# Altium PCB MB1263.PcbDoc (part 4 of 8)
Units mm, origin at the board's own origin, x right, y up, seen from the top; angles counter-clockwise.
Board outline 86 x 120 mm, 6 copper layers (Top Layer, Signal Layer 1, Signal Layer 2, Signal Layer 3, Signal Layer 4, Bottom Layer), stack 1.556 mm thick; 392 components, 421 nets, 1978 pads, 1444 vias.
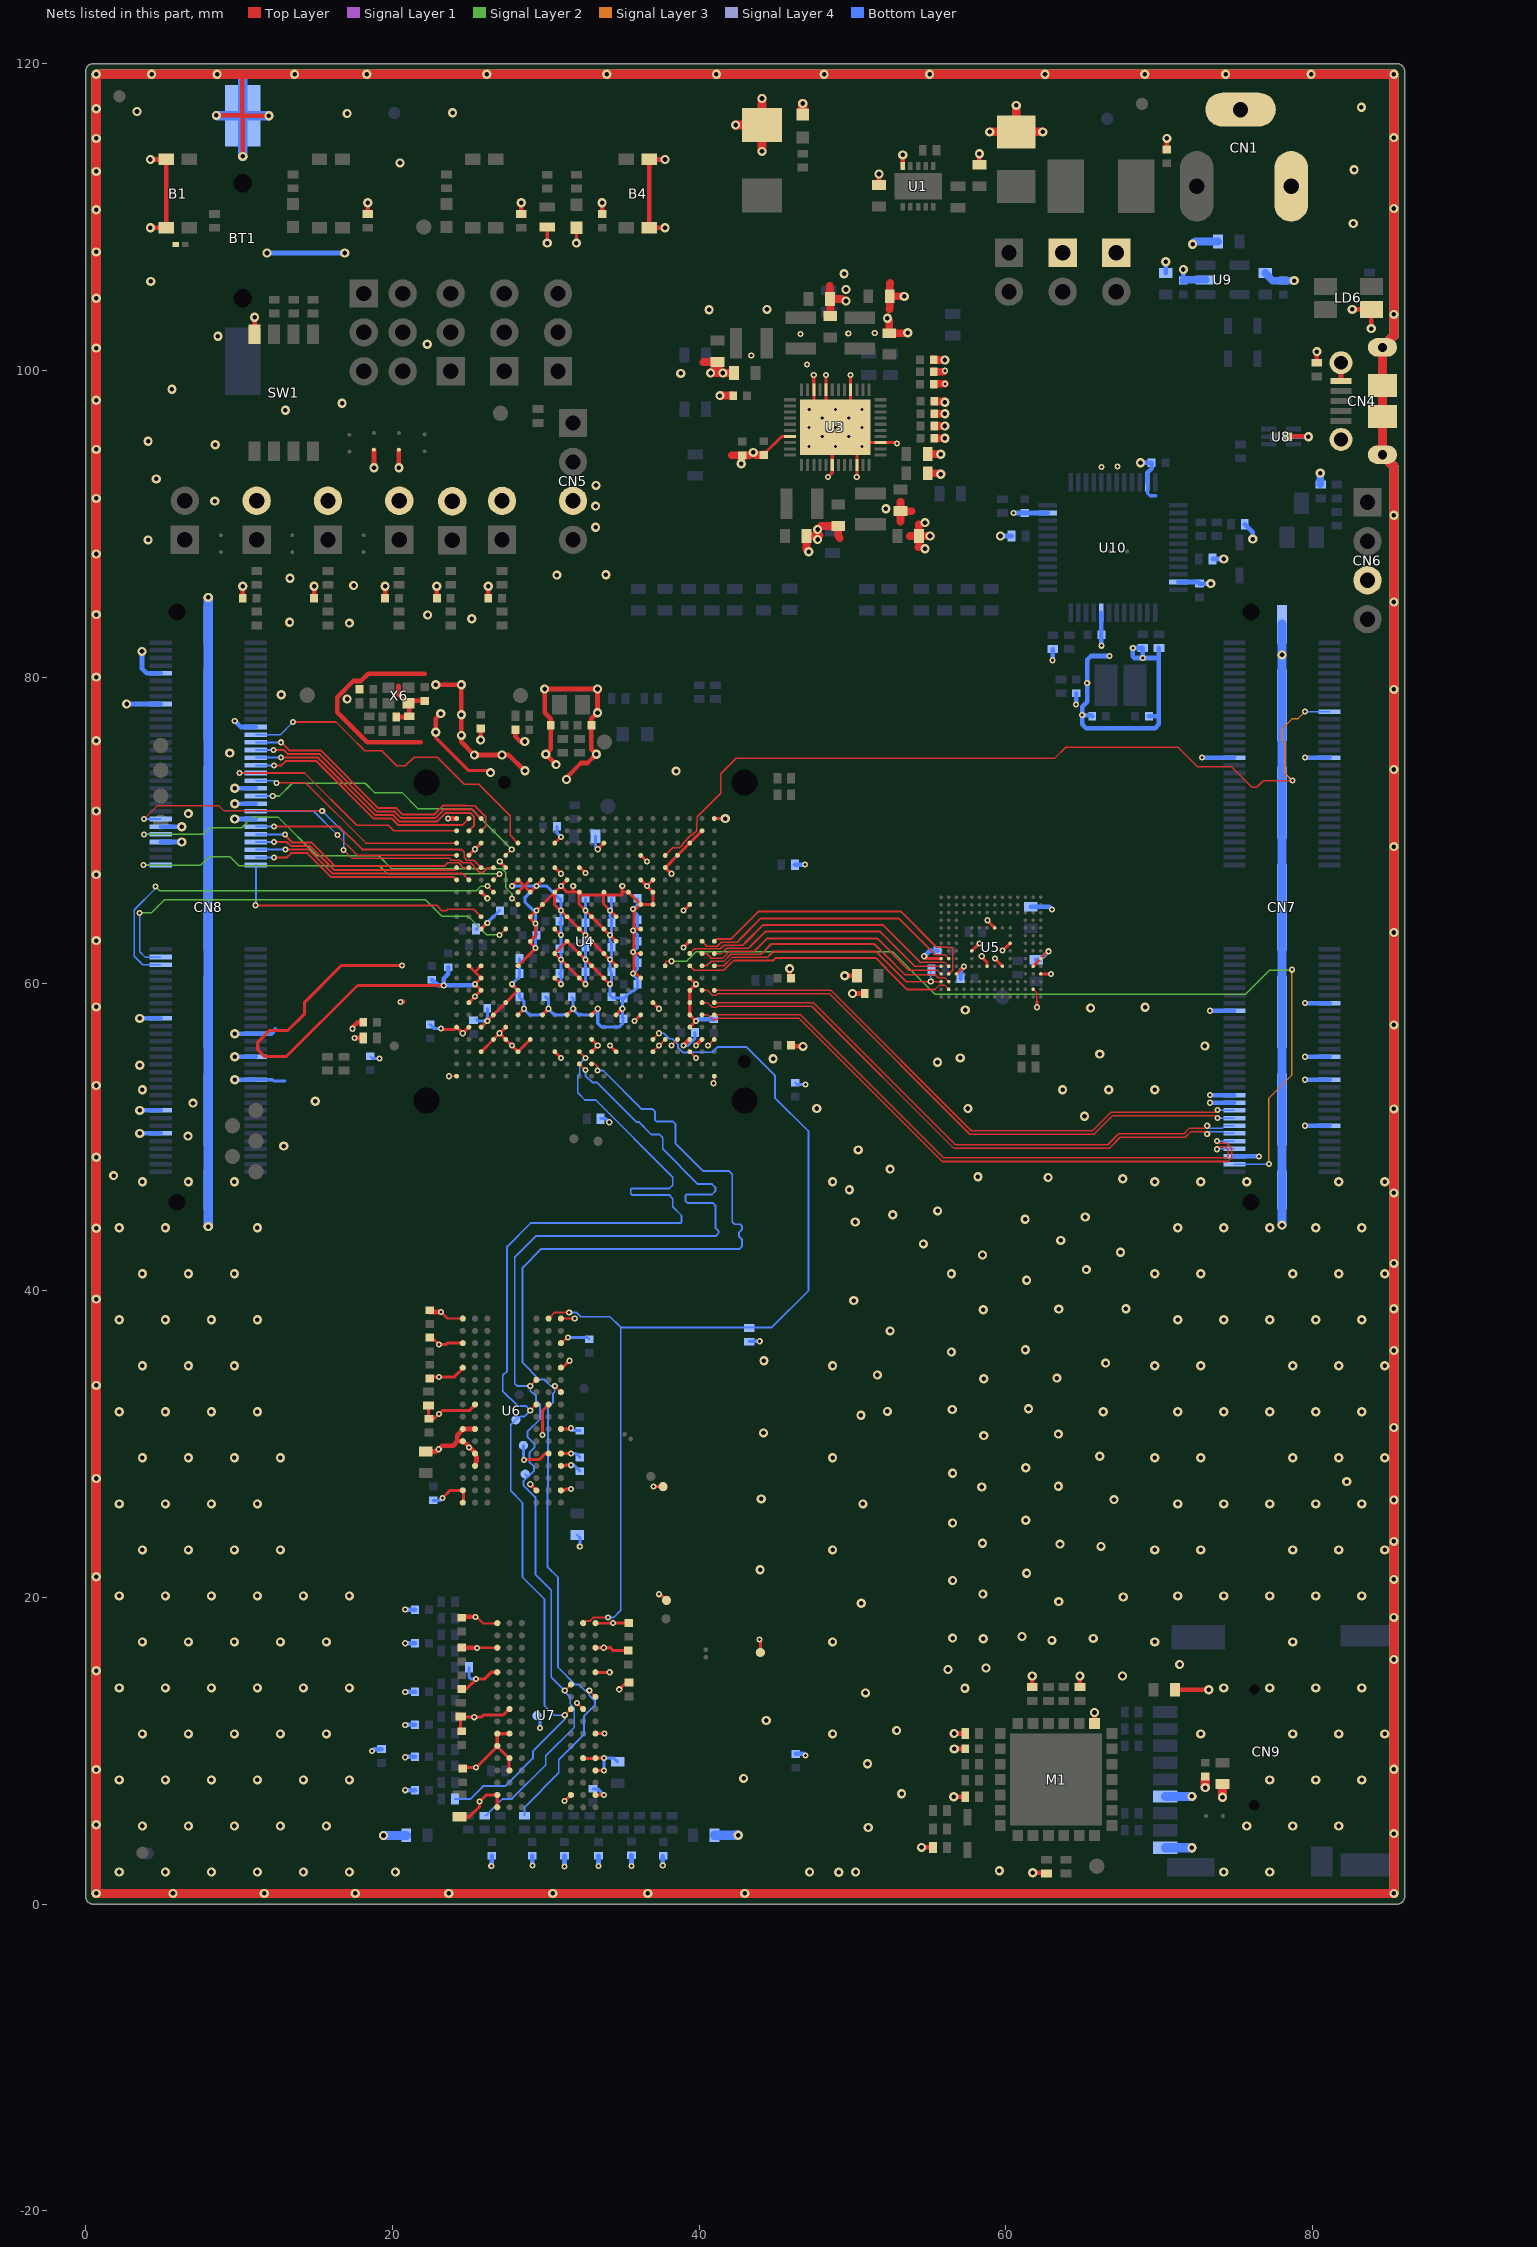
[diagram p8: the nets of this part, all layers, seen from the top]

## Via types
v1: diameter 0.4, hole 0.2, Top Layer to Bottom Layer, tented both sides, 771 vias
v2: diameter 0.6, hole 0.3, Top Layer to Bottom Layer, tented both sides, 670 vias
v3: diameter 0.4, hole 0.2, Top Layer to Bottom Layer, 3 vias

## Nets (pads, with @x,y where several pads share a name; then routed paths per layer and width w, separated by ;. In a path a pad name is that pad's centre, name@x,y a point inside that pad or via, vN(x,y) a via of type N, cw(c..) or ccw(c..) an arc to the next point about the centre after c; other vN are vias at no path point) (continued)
DDR_ODT: R131.1 U4.L21 U6.K1 U7.K1 | length 75.4
  Top Layer w0.12: v1(30.59,33.78) U6.K1@30.99,33.38 ; v1(32.84,13.92) U7.K1@33.24,13.52 ; U4.L21@32.99,54.78 33.21,54.78 33.365,54.625 v1(33.365,54.355)
  Bottom Layer w0.12: R131.1@28.62,5.77 28.62,6.33 30.845,8.555 30.845,9.425 32.5,11.08 32.5,12.28 32.52,12.28 33.2,12.96 33.2,13.269 32.84,13.629 v1(32.84,13.92) 32.83,13.93 32.55,13.93 32.16,14.32 31.931,14.32 30.8,15.451 30.8,21.31 30.104,22.006 30.104,27.185 30.15,27.231 30.15,32.378 30.47,32.698 30.47,33.29 30.59,33.41 v1(30.59,33.78) 30.341,33.78 29.916,34.205 29.585,34.205 28.49,35.3 28.49,41.507 29.703,42.72 42.65,42.72 42.79,42.86 42.79,43.36 42.59,43.56 42.59,43.78 42.79,43.98 42.79,44.23 42.695,44.325 42.335,44.325 42.16,44.5 42.16,47.59 41.96,47.79 40.27,47.79 38.47,49.59 38.47,50.846 38.296,51.02 37.24,51.02 37.12,51.14 37.12,51.684 36.964,51.84 36.256,51.84 33.741,54.355 v1(33.365,54.355)
DDR_RASN: R120.1 TP34.1 U4.M20 U6.J3 U7.J3 | length 77.2
  Top Layer w0.1: U6.J3@29.402,32.599 U6.J3@29.404,32.6
  Top Layer w0.12: v1(28.99,32.18) U6.J3@29.39,32.58 ; v1(31.24,12.32) U7.J3@31.64,12.72 ; U4.M20@32.19,55.58 v1(32.59,55.18)
  Bottom Layer w0.12: R120.1@24.09,6.85 25.07,6.85 25.92,7.7 27.36,7.7 29.165,9.505 29.165,9.985 31.24,12.06 v1(31.24,12.32) 30.54,12.32 29.92,12.94 29.92,19.88 28.484,21.316 28.484,26.176 27.72,26.94 27.72,31.25 TP34.1@28.05,31.58 28.255,31.785 28.595,31.785 v1(28.99,32.18) 28.684,32.486 28.164,32.486 27.2,33.45 27.2,34.473 27.479,34.752 27.479,42.872 29.007,44.4 38.79,44.4 38.85,44.46 38.85,44.9 38.28,45.47 38.28,46 38.04,46.24 35.62,46.24 35.54,46.32 35.54,46.61 35.6,46.67 38.07,46.67 38.28,46.88 38.28,47.404 33.254,52.43 32.56,52.43 32.09,52.9 32.09,54.015 32.215,54.14 32.215,54.805 v1(32.59,55.18)
DDR_RESETN: R103.2 U4.F19 U6.T2 U7.T2 | length 64.4
  Top Layer w0.12: U6.T2@30.19,38.18 30.59,38.58 v1(31.53,38.58) ; U7.T2@32.4,18.31 32.425,18.335 32.549,18.459 32.87,18.459 33.091,18.68 33.37,18.68 33.39,18.7 v1(34.05,18.7) ; U4.F19@36.99,56.38 v1(37.39,56.78)
  Bottom Layer w0.12: v1(31.53,38.58) 31.999,38.58 32.279,38.3 34.19,38.3 34.89,37.6 ; v1(34.05,18.7) 34.41,18.7 34.42,18.69 34.89,19.16 34.89,37.6 ; v1(37.39,56.78) 37.681,56.78 38.041,56.42 38.25,56.42 38.33,56.34 38.339,56.34 38.63,56.049 38.63,55.831 38.931,55.53 39.631,55.53 39.641,55.54 40.87,55.54 41.22,55.89 43.08,55.89 44.94,54.03 44.94,52.588 47.13,50.398 47.13,40 44.73,37.6 43.26,37.6 34.89,37.6
DDR_WEN: R133.1 TP36.1 U4.M21 U6.L3 U7.L3 | length 77.7
  Top Layer w0.12: v1(28.99,33.78) U6.L3@29.39,34.18 ; v1(31.24,13.92) U7.L3@31.64,14.32 ; U4.M21@32.19,54.78 v1(32.59,54.38)
  Bottom Layer w0.12: R133.1@26.02,5.77 26.09,5.77 27.18,6.86 27.79,6.86 30.005,9.075 30.005,9.665 31.86,11.52 31.86,12.791 31.6,13.051 31.6,13.48 31.24,13.84 v1(31.24,13.92) 30.36,14.8 30.36,20.46 29.324,21.496 29.324,26.537 28.54,27.321 28.54,27.57 28.835,27.865 TP36.1@28.85,27.88 ; TP36.1@28.66,28.04 28.82,27.88 TP36.1@28.85,27.88 ; v1(28.99,33.78) 28.99,33.46 29.11,33.34 29.139,33.34 29.37,33.109 29.37,32.82 29.63,32.56 29.63,31.632 28.8,30.802 28.8,30.48 29.26,30.02 29.26,29.76 28.95,29.45 28.95,28.8 29.24,28.51 29.24,28.27 TP36.1@28.85,27.88 ; v1@29.023,33.79 28.99,33.79 28.13,33.79 27.979,33.941 27.979,42.184 29.355,43.56 41.08,43.56 41.28,43.76 41.28,43.876 41.06,44.096 41.06,45.55 40.89,45.72 39.23,45.72 39.12,45.83 39.12,46.21 39.18,46.27 40.84,46.27 41.06,46.49 41.06,46.73 40.84,46.95 39.922,46.95 37.63,49.242 37.63,49.98 37.43,50.18 36.892,50.18 36.072,51 35.908,51 33.328,53.58 33.03,53.58 32.59,54.02 v1(32.59,54.38)
DFSDM_CKOUT: CN8.63 U4.V10 | length 29.4
  Top Layer w0.1: v1@27,63.19 U4.V10@27.39,63.58
  Signal Layer 2 w0.1: v1(3.525,64.625) 4.275,64.625 5.125,65.475 22.175,65.475 23.225,64.425 24.925,64.425 26.16,63.19 v1(26.995,63.19)
  Bottom Layer w0.1: v1(3.525,64.625) 3.525,62.1 3.875,61.75 CN8.63@4.9,61.75
DFSDM_DATA1: CN8.26 U4.U3 | length 21.9
  Top Layer w0.09: 17.7,75.698 18.193,75.205 19.295,75.205 20.275,74.225 20.853,74.225 21.42,74.792 22.922,74.792 24.689,73.025 25.631,73.025 27.695,70.962 27.695,69.675 U4.U3@28.19,69.18
  Top Layer w0.1: v1(13.525,77.075) 16.323,77.075 17.7,75.698
  Bottom Layer w0.1: CN8.26@11.1,76.25 12.7,76.25 v1(13.525,77.075)
DFSDM_DATA3: CN8.65 U4.W7 | length 29.5
  Top Layer w0.1: v1@26.2,66.37 U4.W7@26.59,65.98
  Signal Layer 2 w0.1: v1(4.55,66.35) 4.825,66.075 25.485,66.075 25.785,66.375 v1(26.2,66.375)
  Bottom Layer w0.1: v1(4.55,66.35) 4.55,66.214 3.2,64.864 3.2,64.82 3.175,64.795 3.175,61.8 3.725,61.25 CN8.65@4.9,61.25
DFSDM_DATA5: CN7.20 U4.E4 | length 53.5
  Top Layer w0.09: U4.E4@37.79,68.38 38.285,68.875 38.716,68.875 38.895,69.053 38.895,69.116 39.453,69.675 39.516,69.675 39.829,69.988 39.829,70.519 39.885,70.575 39.885,70.91 41.415,72.44 41.415,73.707 42.433,74.725 42.95,74.725
  Top Layer w0.1: 42.95,74.725 63.2,74.725 63.9,75.425 71.217,75.425 72.492,74.15 74.717,74.15 76.042,72.825 76.35,72.825 76.775,73.25 v1(78.675,73.25)
  Signal Layer 3 w0.1: v1(78.675,73.25) 78.175,73.75 78.175,75.707 78.025,75.857 78.025,76.643 78.682,77.3 79.05,77.3 v1(79.5,77.75)
  Bottom Layer w0.1: v1(79.5,77.75) CN7.20@81.1,77.75
DSI_CK_N: CN7.107 U4.A16 | length 38.4
  Top Layer w0.1: U4.A16@40.99,58.78 47.445,58.78 56.72,49.505 66.64,49.505 67.365,50.23 71.605,50.23 71.975,50.6 72.975,50.6 v1(73.125,50.75)
  Bottom Layer w0.1: v1(73.125,50.75) 73.275,50.6 74.125,50.6 74.275,50.75 CN7.107@74.9,50.75
DSI_CK_P: CN7.109 U4.B16 | length 39.3
  Top Layer w0.1: U4.B16@40.19,58.78 40.551,58.78 40.861,58.47 41.118,58.47 41.198,58.55 47.35,58.55 56.625,49.275 66.735,49.275 67.46,50 71.7,50 72.07,50.37 72.975,50.37 v1(73.125,50.22)
  Bottom Layer w0.1: v1(73.125,50.22) 73.275,50.37 74.155,50.37 74.275,50.25 CN7.109@74.9,50.25
DSI_D0_N: CN7.103 U4.A15 | length 38.3
  Top Layer w0.1: U4.A15@40.99,59.58 48.591,59.58 57.74,50.43 65.655,50.43 66.855,51.63 73.65,51.63 v1(73.8,51.78)
  Bottom Layer w0.1: v1(73.8,51.78) 73.83,51.75 CN7.103@74.9,51.75
DSI_D0_P: CN7.105 U4.B15 | length 39.2
  Top Layer w0.1: U4.B15@40.19,59.58 40.551,59.58 40.861,59.27 41.118,59.27 41.198,59.35 48.495,59.35 57.645,50.2 65.75,50.2 66.95,51.4 73.65,51.4 v1(73.8,51.25)
  Bottom Layer w0.1: v1(73.8,51.25) CN7.105@74.9,51.25
DSI_D1_N: CN7.113 U4.A17 | length 39.8
  Top Layer w0.1: U4.A17@40.99,57.98 46.62,57.98 55.95,48.65 64.425,48.65 64.875,48.65 74.375,48.65 74.5,48.775 74.5,49.175 74.3,49.375 73.937,49.375 73.932,49.37 73.925,49.37 v1(73.775,49.22)
  Bottom Layer w0.1: v1(73.775,49.22) 73.805,49.25 CN7.113@74.9,49.25
DSI_D1_P: CN7.111 U4.B17 | length 41.5
  Top Layer w0.1: U4.B17@40.19,57.98 40.551,57.98 40.861,57.67 41.118,57.67 41.198,57.75 46.525,57.75 55.855,48.42 74.47,48.42 74.73,48.68 74.73,49.27 74.395,49.605 73.92,49.605 v1(73.775,49.75)
  Bottom Layer w0.1: v1(73.775,49.75) CN7.111@74.9,49.75
DSI_RESET: CN8.59 U4.W6 | length 25.6
  Top Layer w0.1: U4.W6@26.59,66.78 v1@26.98,67.17
  Signal Layer 2 w0.1: v1(3.775,67.75) 7.5,67.75 8.025,68.275 9.425,68.275 10,67.7 19.15,67.7 19.68,67.17 v1(26.985,67.17)
  Bottom Layer w0.1: v1(3.775,67.75) CN8.59@4.9,67.75
DSI_TE: CN7.117 U4.E13 | length 58.7
  Top Layer w0.1: U4.E13@37.79,61.18 37.79,61.388 37.876,61.475 v1(38.2,61.475)
  Signal Layer 2 w0.1: v1(38.2,61.475) 39.175,61.475 39.8,62.1 52.6,62.1 55.375,59.325 75.63,59.325 77.205,60.9 78.625,60.9 v1(78.65,60.925)
  Signal Layer 3 w0.1: v1(77.15,48.25) 77.15,52.555 78.65,54.055 v1(78.65,60.925)
  Bottom Layer w0.1: CN7.117@74.9,48.25 v1(77.15,48.25)
EMMC_SDIO2_D0: R900.1 U4.A13 U5.A3 | length 16.8
  Top Layer w0.1: U4.A13@40.99,61.18 41.605,61.18 42.15,61.725 44.45,61.725 44.588,61.863 ; 53.5,60.15 v1(55.1,60.15) U5.A3@55.775,60.15
  Top Layer w0.13: 44.588,61.863 44.85,62.125 51.525,62.125 53.5,60.15
  Bottom Layer w0.09: v1(55.1,60.15) 55.1,60.85 R900.1@55.15,60.9
EMMC_SDIO2_D1: U4.B12 U5.A4 | length 17.2
  Top Layer w0.09: U4.B12@40.19,61.98 40.495,61.98 40.8,61.675 41.458,61.675 41.463,61.68 41.546,61.68 41.548,61.681
  Top Layer w0.1: 41.544,61.685 41.984,62.125 43.6,62.125 43.825,62.35 ; 53.675,60.9 55.525,60.9 U5.A4@55.775,60.65
  Top Layer w0.13: 43.825,62.35 44.45,62.975 51.6,62.975 53.675,60.9
EMMC_SDIO2_D2: U4.A12 U5.A5 | length 16.4
  Top Layer w0.1: U4.A12@40.99,61.98 41.455,61.98 41.8,62.325 43.225,62.325 43.35,62.45 ; 54.1,61.15 U5.A5@55.775,61.15 U5.A5@55.725,61.1
  Top Layer w0.13: 43.35,62.45 44.3,63.4 51.8,63.4 54.05,61.15 54.1,61.15
EMMC_SDIO2_D3: U4.C13 U5.B2 | length 18.4
  Top Layer w0.09: U4.C13@39.39,61.18 39.695,60.875 41.599,60.875 42.124,61.4 ; 55.668,59.9 55.882,59.9
  Top Layer w0.1: 42.124,61.4 42.249,61.525 44.825,61.525 ; 55.373,59.63 55.643,59.9 55.668,59.9 ; 55.882,59.9 56.025,59.9 U5.B2@56.275,59.65
  Top Layer w0.13: 44.825,61.525 44.975,61.675 51.534,61.675 52.175,61.034 52.175,61.02 53.565,59.63 55.373,59.63
EMMC_SDIO2_D4: U4.B13 U5.B3 | length 17.7
  Top Layer w0.09: U4.B13@40.19,61.18 40.48,61.18 40.785,61.485 41.544,61.485 ; 42.067,61.925 44.025,61.925 44.137,62.037 ; 53.426,60.6 55.401,60.6 55.601,60.4 55.949,60.4
  Top Layer w0.1: 41.544,61.485 41.627,61.485 42.067,61.925 ; 52.101,61.925 53.426,60.6 ; 55.949,60.4 56.025,60.4 56.199,60.226 56.199,60.15 U5.B3@56.275,60.15
  Top Layer w0.13: 44.137,62.037 44.7,62.6 51.426,62.6 52.101,61.925
EMMC_SDIO2_D5: U4.A11 U5.B4 | length 19.1
  Top Layer w0.09: 55.475,62.4 56.4,62.4 56.525,62.275 56.525,60.9 U5.B4@56.275,60.65
  Top Layer w0.13: U4.A11@40.99,62.78 41.15,62.94 42.09,62.94 43.875,64.725 53.15,64.725 55.475,62.4
EMMC_SDIO2_D6: U4.C12 U5.B5 | length 18.8
  Top Layer w0.09: U4.C12@39.39,61.98 39.685,62.275 41.375,62.275 41.625,62.525 42.85,62.525 43.025,62.7 ; 55.601,61.4 55.949,61.4
  Top Layer w0.1: 54.425,61.4 55.601,61.4 ; 55.949,61.4 56.025,61.4 U5.B5@56.275,61.15
  Top Layer w0.13: 43.025,62.7 44.15,63.825 52,63.825 54.425,61.4
EMMC_SDIO2_D7: U4.B11 U5.B6 | length 18.1
  Top Layer w0.09: U4.B11@40.19,62.78 40.505,62.465 41.19,62.465 41.45,62.725 42.475,62.725 42.675,62.925 ; 55.601,61.9 55.949,61.9
  Top Layer w0.1: 55.225,62.075 55.4,61.9 55.601,61.9 ; 55.949,61.9 56.025,61.9 U5.B6@56.275,61.65
  Top Layer w0.13: 42.675,62.925 44.025,64.275 53.025,64.275 55.225,62.075
ETH_CLK125: CN8.51 U4.U8 | length 29
  Top Layer w0.1: v1@27.8,65.57 U4.U8@28.19,65.18
  Signal Layer 2 w0.1: v1(3.8,69.75) 7.725,69.75 8.15,70.175 10.175,70.175 10.85,70.85 12.575,70.85 15.075,68.35 19.109,68.35 19.94,67.52 27.13,67.52 27.4,67.249 27.4,66.26 27.8,65.86 v1(27.8,65.575)
  Bottom Layer w0.1: v1(3.8,69.75) CN8.51@4.9,69.75
ETH_GTX_CLK: CN8.46 U4.AB4 | length 14.3
  Top Layer w0.1: v1(16.425,69.7) 16.425,69.675 17.72,68.38 U4.AB4@24.19,68.38
  Bottom Layer w0.1: CN8.46@11.1,71.25 14.875,71.25 v1(16.425,69.7)
ETH_MDC: CN8.38 U4.AB3 | length 14.8
  Top Layer w0.1: v1(12.45,73.1) 14.359,73.1 18.28,69.18 U4.AB3@24.19,69.18
  Bottom Layer w0.1: CN8.38@11.1,73.25 12.3,73.25 v1(12.45,73.1)
ETH_MDINT: CN8.47 U4.W5 | length 26.9
  Top Layer w0.09: 23.725,68.175 23.825,68.075 24.395,68.075 24.585,67.885 25.116,67.885 25.295,67.706 25.295,67.643 25.663,67.275 25.916,67.275 26.221,67.58 U4.W5@26.59,67.58
  Top Layer w0.1: v1(3.8,70.75) 4.65,71.6 8.7,71.6 9.025,71.275 v1(15.425,71.275) ; v1(16.825,68.725) 17.37,68.18 23.72,68.18 23.725,68.175
  Bottom Layer w0.1: v1(3.8,70.75) CN8.47@4.9,70.75 ; v1(15.425,71.275) 16.817,69.883 16.817,68.733 v1(16.825,68.725)
ETH_MDIO: CN8.36 U4.AB2 | length 16.8
  Top Layer w0.09: 19.275,70.35 19.725,70.35 20.095,69.98 20.52,69.98
  Top Layer w0.1: v1(10.025,73.75) 14.275,73.75 17.675,70.35 19.275,70.35 ; 20.52,69.98 U4.AB2@24.19,69.98
  Bottom Layer w0.1: v1(10.025,73.75) CN8.36@11.1,73.75
ETH_RX_CLK: CN8.42 U4.V4 | length 19.4
  Top Layer w0.1: U4.V4@27.39,68.38 v1@27.779,68.77
  Signal Layer 2 w0.1: v1(12.2,72.25) 12.633,72.25 13.466,73.084 18.226,73.084 18.834,72.475 20.625,72.475 21.675,71.425 25.13,71.425 v1(27.785,68.77)
  Bottom Layer w0.1: CN8.42@11.1,72.25 v1(12.2,72.25)
ETH_RX_DV: CN8.60 U4.Y9 | length 17.7
  Top Layer w0.09: 22.65,65.125 22.883,65.125 23.225,64.783 23.519,64.783 23.611,64.875 25.295,64.875 U4.Y9@25.79,64.38
  Top Layer w0.13: v1(11.075,65.125) 22.65,65.125
  Bottom Layer w0.13: v1(11.075,65.125) 11.1,65.15 CN8.60@11.1,67.75
ETH_RXD0: CN8.58 U4.AB6 | length 13.9
  Top Layer w0.13: v1(12.275,68.25) 13.13,68.25 13.4,68.52 14.454,68.52 16.009,66.965 24.005,66.965 U4.AB6@24.19,66.78
  Bottom Layer w0.13: CN8.58@11.1,68.25 v1(12.275,68.25)
ETH_RXD1: CN8.56 U4.AA6 | length 14.7
  Top Layer w0.13: v1(13.025,68.75) 14.549,68.75 16.104,67.195 24.575,67.195 U4.AA6@24.99,66.78
  Bottom Layer w0.13: CN8.56@11.1,68.75 v1(13.025,68.75)
ETH_RXD2: CN8.54 U4.AB5 | length 13.9
  Top Layer w0.13: v1(12.275,69.25) 13.125,69.25 13.395,68.98 14.645,68.98 16.2,67.425 24.035,67.425 U4.AB5@24.19,67.58
  Bottom Layer w0.13: CN8.54@11.1,69.25 v1(12.275,69.25)
ETH_RXD3: CN8.52 U4.AA5 | length 15
  Top Layer w0.09: 23.6,67.885 24.316,67.885 24.621,67.58 U4.AA5@24.99,67.58
  Top Layer w0.13: v1(13,69.75) 13,69.7 13.49,69.21 14.74,69.21 16.275,67.675 23.39,67.675 23.6,67.885
  Bottom Layer w0.13: CN8.52@11.1,69.75 v1(13,69.75)
ETH_TX_EN: CN8.50 U4.Y5 | length 16
  Top Layer w0.09: 24.685,68.59 24.685,68.253 24.863,68.075 25.295,68.075 U4.Y5@25.79,67.58
  Top Layer w0.13: v1(12.275,70.25) 16.55,70.25 18.025,68.775 24.5,68.775 24.685,68.59
  Bottom Layer w0.13: CN8.50@11.1,70.25 v1(12.275,70.25)
ETH_TXD0: CN8.34 U4.AA1 | length 15.9
  Top Layer w0.13: v1(12.275,74.25) 12.766,74.25 13.036,74.52 15.055,74.52 18.8,70.775 19.975,70.775 20.4,70.35 24.56,70.35 U4.AA1@24.99,70.78
  Bottom Layer w0.13: CN8.34@11.1,74.25 v1(12.275,74.25)
ETH_TXD1: CN8.32 U4.AA2 | length 17.3
  Top Layer w0.13: v1(12.75,74.75) 15.15,74.75 18.895,71.005 20.07,71.005 20.495,70.58 22.904,70.58 23.469,71.145 25.084,71.145 25.315,70.914 25.315,70.305 U4.AA2@24.99,69.98
  Bottom Layer w0.13: CN8.32@11.1,74.75 v1(12.75,74.75)
ETH_TXD2: CN8.30 U4.Y1 | length 17
  Top Layer w0.13: v1(12.25,75.25) 12.925,75.25 13.175,75 15.226,75 18.991,71.235 20.166,71.235 20.591,70.81 22.809,70.81 23.374,71.375 25.195,71.375 U4.Y1@25.79,70.78
  Bottom Layer w0.13: CN8.30@11.1,75.25 v1(12.25,75.25)
ETH_TXD3: CN8.28 U4.Y2 | length 18.5
  Top Layer w0.09: 24.726,71.626 25.375,71.626 26.095,70.906 26.095,70.285 U4.Y2@25.79,69.98
  Top Layer w0.13: v1(12.75,75.75) 13.27,75.23 15.321,75.23 19.086,71.465 20.261,71.465 20.686,71.04 22.713,71.04 23.299,71.626 24.726,71.626
  Bottom Layer w0.13: CN8.28@11.1,75.75 v1(12.75,75.75)
GND: B1.3 B1.4 B4.1 B4.2 BT1.2 C1.2 C2.1 C3.1 C4.1 C5.1 C6.1 C7.1 C8.1 C9.1 C10.1 C11.1 C12.1 C13.1 C14.1 C15.1 C16.1 C17.1 C18.1 C19.1 C20.2 C21.1 C22.1 C23.1 C24.1 C25.1 C26.1 C27.1 C28.1 C29.1 C30.1 C31.1 C32.1 C33.1 C34.1 C35.1 C36.2 C37.1 C38.1 C39.2 C40.1 C41.1 C42.2 C43.1 C44.2 C45.2 C46.2 C47.2 C48.1 C49.2 C50.2 C51.2 C52.2 C53.2 C54.2 C55.1 C56.2 C57.2 C58.1 C59.1 C60.1 C61.2 C62.2 C63.1 C64.1 C65.2 C66.2 C67.1 C68.1 C69.1 C70.1 C71.1 C72.2 C73.2 C74.2 C75.1 C76.1 C77.1 C78.1 C79.1 C80.1 C81.2 C82.1 C83.1 C84.1 C85.1 C86.1 C87.1 C88.1 C89.1 C90.1 C91.1 C92.1 C93.1 C94.1 C95.2 C96.1 C97.1 C98.1 C99.1 C100.1 C101.1 C102.1 C103.1 C104.1 C105.1 C106.1 C107.1 C108.1 C109.1 C110.1 C111.1 C112.1 C113.1 C114.1 C115.2 C116.2 C117.2 C118.2 C119.2 C120.2 C121.2 C122.1 C123.2 C124.2 C125.2 C126.2 C127.2 C128.2 C129.2 C130.1 C131.2 C132.2 C133.1 C134.1 C135.2 C136.2 C137.2 C138.2 C139.2 C140.2 C300.1 CN1.2 CN1.3 CN4.5 CN4.6 CN4.7 CN4.8 CN4.9 CN4.10 CN4.11 CN5.3 CN6.3 CN7.31 CN7.32 CN7.76 CN7.77 CN7.90 CN7.96 CN7.99 CN7.101 CN7.108 CN7.115 CN7.121 CN7.122 CN7.123 CN7.124 CN7.125 CN7.126 CN7.127 CN7.128 CN8.9 CN8.17 CN8.24 CN8.40 CN8.44 CN8.48 CN8.49 CN8.53 CN8.79 CN8.84 CN8.90 CN8.96 CN8.103 CN8.109 CN8.121 CN8.122 CN8.123 CN8.124 CN8.125 CN8.126 CN8.127 CN8.128 CN9.6 CN9.9 D1.1 JP1.1 JP2.1 JP7.2 JP8.2 JP9.2 JP10.2 JP11.2 LD1.2 LD4.2 LD5.2 LD6.1 M1.21 R9.2 R10.2 R14.1 R32.1 R36.1 R37.1 R40.1 R41.1 R44.1 R47.1 R48.1 R55.1 R65.2 R69.2 R73.1 R74.2 R88.2 R89.2 R91.1 R97.2 R98.2 R102.2 R103.1 R108.1 R303.2 SB2.1 SB3.1 SW1.4 TP23.1 TP24.1 TP26.1 TP35.1 TP37.1 U1.10 U2.2 U3.6 U3.10 U3.15 U3.26 U3.30 U3.32 U3.41 U3.ep U4.A1 U4.A19 U4.A22 U4.AA4 U4.AA13 U4.AA16 U4.AA18 U4.AB1 U4.AB18 U4.AB22 U4.B2 U4.B19 U4.C3 U4.C8 U4.C11 U4.C14 U4.C15 U4.C16 U4.C17 U4.C18 U4.C19 U4.C20 U4.D4 U4.D19 U4.E5 U4.E19 U4.F6 U4.F7 U4.F8 U4.F16 U4.F20 U4.G4 U4.G6 U4.G8 U4.G10 U4.G12 U4.G14 U4.G17 U4.H7 U4.J9 U4.J11 U4.J13 U4.J17 U4.J20 U4.K3 U4.K7 U4.K10 U4.K12 U4.K14 U4.L9 U4.L11 U4.L13 U4.L17 U4.L19 U4.L20 U4.M5 U4.M7 U4.M10 U4.M12 U4.M14 U4.N6 U4.N9 U4.N11 U4.N13 U4.N17 U4.P3 U4.P5 U4.P7 U4.P10 U4.P12 U4.P14 U4.P20 U4.R6 U4.R8 U4.R17 U4.T6 U4.T7 U4.T9 U4.T11 U4.T19 U4.U6 U4.U7 U4.U13 U4.U15 U4.U17 U4.U20 U4.V5 U4.V16 U4.V18 U4.V19 U4.W17 U4.W19 U4.Y3 U4.Y7 U4.Y10 U4.Y13 U4.Y14 U4.Y15 U4.Y18 U4.Y20 U5.A6 U5.C4 U5.E7 U5.G5 U5.H10 U5.J5 U5.K8 U5.N2 U5.N5 U5.P4 U5.P6 U6.A9 U6.B1 U6.B3 U6.B9 U6.D1 U6.D8 U6.E1 U6.E2 U6.E8 U6.F9 U6.G1 U6.G8 U6.G9 U6.J2 U6.J8 U6.M1 U6.M9 U6.P1 U6.P9 U6.T1 U6.T9 U7.A9 U7.B1 U7.B3 U7.B9 U7.D1 U7.D8 U7.E1 U7.E2 U7.E8 U7.F9 U7.G1 U7.G8 U7.G9 U7.J2 U7.J8 U7.M1 U7.M9 U7.P1 U7.P9 U7.T1 U7.T9 U8.2 U9.2 U10.8 U10.23 U10.35 U10.47 X6.2 | length 2663.5
  Top Layer w0.09: 62.025,58.85 62.025,59.257
  Top Layer w0.1: U5.N2@61.775,59.65 62.025,59.4 62.025,59.257
  Top Layer w0.12: v1(23.69,53.98) U4.AB22@24.19,53.98 ; v1@29.048,27.322 v1@29.048,27.38 ; U6.M1@30.99,34.98 U6.M1@31.09,34.98 ; v1@31.59,30.98 v1(31.64,31.03) ; U4.M5@32.19,67.58 U4.M5@32.19,67.63 ; U4.F20@36.99,55.58 v1(37.39,55.98) U4.E19@37.79,56.38 ; v1(37.39,20.21) v1@37.47,20.21 ; v1(38.19,55.98) U4.D19@38.59,56.38 ; U4.C20@39.39,55.58 v1(39.79,55.18) ; v1(40.59,55.98) U4.A19@40.99,56.38 ; v1(40.94,53.52) 40.99,53.57 U4.A22@40.99,53.98
  Top Layer w0.15: v1@23.17,38.61 23.175,38.605 23.6,38.18 U6.T9@24.59,38.18 U6.T9@24.64,38.18 ; U6.M9@24.59,34.93 U6.M9@24.59,34.98 ; v1(25.41,18.73) 25.495,18.73 25.92,18.305 26.825,18.305 U7.T9@26.84,18.32 ; v1(25.52,16.71) U7.P9@26.8,16.71 ; U6.T1@30.99,38.18 v1(31.89,38.18) ; U6.P1@31.015,36.555 31.4,36.94 v1(31.45,36.94) ; U7.T1@33.2,18.31 33.24,18.31 v1@34.39,18.31
  Top Layer w0.2: v1(20.625,61.2) 16.675,61.2 14.279,58.804 14.279,58.054 13.2,56.975 12,56.975 11.225,56.2 11.225,55.7 11.65,55.275 13.1,55.275 17.725,59.9 v1(23.35,59.9) ; R36.1@22.315,32.38 22.36,32.335 C47.2@22.36,31.65 ; C47.2@22.39,31.65 22.72,31.65 v1(23.03,31.96) 23.25,32.18 25.013,32.18 25.401,32.569 U6.J8@25.433,32.6 ; C46.2@22.44,34.18 22.44,34.205 22.467,34.232 22.615,34.38 v1(23.04,34.38) 24.04,34.38 U6.M9@24.59,34.93 ; C45.2@22.53,36.84 C45.2@22.43,36.94 22.59,36.94 v1(23.04,36.49) 23.51,36.49 23.62,36.6 24.57,36.6 U6.P9@24.59,36.58 ; v2(22.825,76.4) 22.825,76.056 24.956,73.925 26.255,73.925 v2(26.401,73.779) ; v1(23.165,57.08) 23.215,57.03 24.04,57.03 U4.AB18@24.19,57.18 v1(24.59,56.78) U4.AA18@24.99,57.18 ; v1(23.27,26.48) 23.77,26.98 U6.B9@24.59,26.98 ; C59.1@24.38,5.7 25.02,5.7 25.69,6.37 v1(25.69,6.69) 26.12,7.12 U7.B9@26.84,7.12 26.84,6.35 26.825,6.335 U7.A9@26.79,6.3 ; C53.2@24.52,14.02 24.82,14.02 24.82,14.03 v1(25.46,14.67) 25.995,14.67 26.445,15.12 U7.M9@26.84,15.12 ; C65.2@24.53,11.27 24.525,11.275 24.45,11.35 R55.1@24.45,12.23 24.49,12.19 v1(25.34,12.19) 25.79,12.19 25.93,12.33 27.22,12.33 U7.J8@27.6,12.71 ; C66.2@24.58,8.85 24.64,8.91 v1(25.46,8.91) U7.F9@26.83,10.28 ; U6.A9@24.64,26.18 U6.B9@24.64,26.98 ; U4.AA16@24.99,58.78 v1(25.39,59.18) U4.Y15@25.79,59.58 ; U4.AA13@24.99,61.22 U4.AA13@24.99,61.18 25.39,60.78 ; U4.AA4@24.99,68.38 v1(25.39,68.78) U4.Y3@25.79,69.18 ; U4.Y7@25.79,65.98 v1(26.19,65.58) ; U4.Y20@25.79,55.58 U4.W19@26.59,56.38 ; U4.Y18@25.79,57.18 v1(26.19,57.58) U4.W17@26.59,57.98 U4.V16@27.39,58.78 U4.U15@28.19,59.58 ; U4.Y15@25.79,59.58 v1(25.39,59.98) U4.Y14@25.79,60.38 25.39,60.78 ; U4.Y13@25.79,61.18 25.39,60.78 ; U4.Y10@25.79,63.58 v1(26.19,63.98) ; U4.W19@26.59,56.38 v1(26.99,56.78) ; U7.F9@26.8,10.31 26.815,10.295 U7.F9@26.83,10.28 ; U7.G9@26.84,11.12 U7.G9@26.84,11.11 ; v1@27,67.97 U4.V5@27.39,67.58 ; U4.V18@27.39,57.18 v1(26.99,56.78) ; U7.D8@27.6,8.71 27.6,8.72 27.6,9.51 U7.F9@26.83,10.28 ; U7.G8@27.6,11.11 U7.G9@26.84,11.11 ; v1(27.79,59.98) U4.U15@28.19,59.58 ; v1(27.79,66.38) 27.86,66.45 27.925,66.515 U4.U6@28.19,66.78 28.59,66.38 ; U4.U17@28.19,57.98 v1(28.59,58.38) ; U4.U13@28.19,61.18 v1(29.34,62.33) 28.99,62.68 U4.T11@28.99,62.78 29.34,63.13 v1(29.34,63.93) 28.99,64.28 U4.T9@28.99,64.38 v1(29.39,64.78) U4.R8@29.79,65.18 U4.P7@30.565,65.955 ; U4.U7@28.19,65.98 28.198,65.988 28.59,66.38 ; v1@28.59,28.98 29.57,28.98 29.97,29.38 U6.E2@30.19,29.38 U6.E2@30.24,29.38 ; U4.T19@28.99,56.38 28.66,56.05 U4.U20@28.19,55.58 v1(27.79,55.98) U4.V19@27.39,56.38 v1(26.99,56.78) ; U4.T6@28.99,66.78 28.59,66.38 ; v1@29.048,27.322 U6.B3@29.39,26.98 ; v1(29.79,30.58) 29.79,32.18 U6.J2@30.19,32.58 ; U4.R17@29.79,57.98 v1(30.19,58.38) ; U4.R6@29.79,66.78 v1(29.39,66.38) U4.T7@28.99,65.98 28.59,66.38 ; v2(30.1,108.3) LD5.2@30.1,109.35 ; U4.P20@30.59,55.58 v1(30.99,55.18) ; U4.P14@30.59,60.38 v1(30.99,59.98) ; U4.P10@30.59,63.58 v1(30.99,63.18) ; U4.P5@30.59,67.58 v1(30.99,67.18) ; U4.P3@30.59,69.18 v1(30.99,69.58) ; U6.B1@30.99,26.98 31.22,26.98 31.32,27.08 v1(31.64,27.08) ; U6.D1@30.99,28.58 31.25,28.58 31.3,28.63 31.63,28.63 v1(31.64,28.62) ; U6.E1@30.99,29.38 v1(31.64,29.38) v1@31.725,29.38 ; U6.G1@30.99,30.98 v1@31.59,30.98 ; U6.M1@31.09,34.98 v1(31.54,35.43) ; v1(31.23,6.725) U7.B3@31.625,7.12 ; U4.N17@31.39,57.98 v1(31.79,58.38) ; U4.N6@31.39,66.78 v1(30.99,66.38) ; v1(31.79,66.38) 31.79,65.98 ; v2(32,108.3) LD4.2@32,109.3 ; v1(32.04,13.12) U7.J2@32.44,12.72 ; U4.M5@32.19,67.63 32.215,67.605 v1(32.59,67.23) ; U7.E2@32.44,9.51 U7.E1@33.24,9.51 ; v1(32.59,59.98) 32.19,60.38 31.39,61.18 v1(30.99,61.58) U4.P12@30.59,61.98 U4.N11@31.39,62.78 32.19,61.98 32.19,61.97 32.2,61.97 v1(32.59,61.58) 32.99,61.18 U4.K14@33.79,60.38 v1(34.19,59.98) ; U4.L20@32.99,55.58 v1(33.39,55.98) U4.L19@32.99,56.38 ; U4.L17@32.99,57.98 v1(33.39,58.38) ; U7.M1@33.2,15.11 33.24,15.11 v1@34.17,15.11 ; U7.B1@33.24,7.12 v1(33.79,7.12) ; U7.D1@33.24,8.72 v1(33.79,8.72) ; U7.E1@33.24,9.52 v1(33.79,9.52) ; U7.G1@33.24,11.12 v1(33.83,11.12) ; U7.P1@33.24,16.72 v1(33.78,16.72) 34.22,16.72 34.41,16.53 C52.2@35.39,16.53 ; v1(33.39,68.78) U4.K3@33.79,69.18 ; v1(34.19,55.98) U4.J20@34.59,55.58 ; v1(34.39,18.33) C50.2@35.4,18.33 ; U4.J17@34.59,57.98 v1(34.99,58.38) ; U4.J13@34.59,61.18 v1(34.19,61.58) U4.K12@33.79,61.98 32.99,62.78 v1(32.59,63.18) 32.19,63.58 31.39,64.38 v1(30.99,64.78) 30.94,64.78 30.565,65.155 U4.P7@30.565,65.955 ; U4.J11@34.59,62.78 v1(34.19,63.18) U4.K10@33.79,63.58 32.99,64.38 v1(32.59,64.78) 32.165,65.205 32.165,65.955 U4.M7@32.19,65.98 ; U4.J9@34.59,64.38 v1(34.19,64.78) 33.765,65.205 U4.K7@33.765,65.955 ; v1(34.79,14.01) 35.23,14.45 C54.2@35.43,14.45 ; v1(34.99,66.38) 34.965,66.355 34.965,65.98 ; v1(35.79,57.58) U4.G17@36.19,57.98 ; U4.G14@36.19,60.38 35.89,60.68 v1(35.69,60.68) 35.75,60.74 v1@35.75,62.02 ; U4.G12@36.19,61.98 35.79,61.98 v1@35.75,62.02 ; U4.G10@36.19,63.58 35.79,63.58 v1@35.75,63.54 ; U4.G6@36.19,66.78 v1(36.59,66.38) ; U4.G4@36.19,68.38 v1(36.59,67.98) ; U4.F6@36.99,66.78 v1(36.59,66.38) ; U4.F16@36.99,58.78 v1(37.39,58.38) ; v1(37.02,27.22) TP23.1@37.65,27.22 ; v1@37.47,20.21 TP24.1@37.87,19.81 ; v1(38.19,67.18) U4.E5@37.79,67.58 U4.D4@38.59,68.38 U4.C3@39.39,69.18 U4.B2@40.19,69.98 ; v1(38.99,62.38) U4.C11@39.39,62.78 ; v1(38.99,64.78) U4.C8@39.39,65.18 ; U4.C18@39.39,57.18 v1(39.79,57.58) U4.C17@39.39,57.98 U4.C16@39.39,58.78 U4.C15@39.39,59.58 39.39,59.585 39.755,59.95 39.755,59.98 39.755,60.03 39.397,60.387 U4.C14@39.395,60.39 ; U4.A1@40.99,70.78 41.705,70.78 v2(41.71,70.775) ; v1(43.94,17.25) 43.99,17.2 TP26.1@43.99,16.41 ; C20.2@44.202,94.51 45.378,95.686 U3.41@45.929,95.686 ; U3.ep@46.814,95.686 U3.ep@46.9,95.6 ; v1(47.475,99.7) 47.475,98.74 U3.32@47.479,98.736 47.479,98.021 U3.ep@47.5,98 ; v1@48.279,99.7 U3.30@48.279,98.736 48.279,97.921 U3.ep@48.3,97.9 ; v1(48.396,93.05) 48.679,93.333 U3.6@48.679,93.836 48.679,94.579 U3.ep@48.7,94.6 ; v1(49.875,99.7) 49.879,99.696 U3.26@49.879,98.736 49.879,97.721 U3.ep@49.9,97.7 ; v1(50.275,93.05) 50.279,93.054 U3.10@50.279,93.836 50.279,94.679 U3.ep@50.3,94.7 ; U3.ep@51,95.3 51.014,95.286 U3.15@51.829,95.286 52.839,95.286 v1(52.9,95.225) ; v1(54.675,61.8) 54.825,61.65 U5.A6@55.775,61.65 ; U5.C4@56.775,60.65 57.25,61.125 v1(57.275,61.125) ; U5.E7@57.775,62.15 58.25,62.625 v1(58.275,62.625) ; v1(58.425,61.8) 58.425,61.75 58.775,61.4 U5.G5@58.775,61.15 ; v1(58.8,64.15) 58.8,64.125 U5.H10@59.275,63.65 ; v1(59.3,61.65) 59.3,61.625 U5.J5@59.775,61.15 ; v1(59.775,62.175) 59.8,62.175 U5.K8@60.275,62.65 ; U5.N5@61.775,61.15 U5.P6@62.275,61.65 62.75,62.125 v1(62.775,62.125) ; v1(62.025,58.475) 62.025,58.85 ; U5.P4@62.275,60.65 v1(62.95,60.65) ; U7.F9@26.83,10.28 26.84,10.29 U7.F9@26.84,10.32 U7.G9@26.84,11.11 ; U4.P7@30.565,65.955 U4.P7@30.59,65.98 v1(30.99,66.38) ; v1(30.99,66.38) 31.39,65.98 31.79,65.98 ; 31.79,65.98 U4.M7@32.19,65.98 ; U4.M7@32.19,65.98 32.37,65.8 33.61,65.8 U4.K7@33.765,65.955 ; U4.K7@33.765,65.955 U4.K7@33.79,65.98 33.969,65.8 34.965,65.8 34.965,65.98 ; 34.965,65.98 U4.H7@35.39,65.98 U4.G8@36.19,65.18 ; v1@35.75,62.02 v1(35.69,62.08) 35.75,62.14 35.75,63.42 v1(35.69,63.48) v1@35.75,63.54 ; v1@35.75,63.54 35.75,64.82 v1(35.69,64.88) 35.89,64.88 U4.G8@36.19,65.18 ; U4.G8@36.19,65.18 U4.F8@36.99,65.18 U4.F7@36.99,65.98 v1(36.59,66.38)
  Top Layer w0.3: v2(4.225,109.3) B1.4@5.25,109.3 B1.3@5.25,113.75 v2(4.225,113.75) ; v2(8.525,116.625) 10.225,116.625 ; 10.225,119.3 10.225,116.625 ; C28.1@10.25,85.15 v2(10.25,85.925) ; v2(10.25,113.95) 10.25,116.55 10.225,116.575 10.25,116.6 ; SW1.4@11.015,102.345 v2(11.015,103.46) ; v2(11.95,116.6) 10.25,116.6 ; C29.1@14.9,85.15 v2(14.9,85.925) ; v1(17.4,57.075) 17.4,57.168 17.732,57.5 C42.2@18.1,57.5 ; v1(17.525,56.475) R32.1@18.1,56.475 ; R9.2@18.4,110.2 v2(18.4,110.925) ; v2(18.8,93.65) SB2.1@18.8,94.825 ; C30.1@19.525,85.15 v2(19.525,85.925) ; C35.1@20.25,77.4 21.05,77.4 R303.2@21.1,77.45 21.1,78.25 X6.2@21.05,78.3 ; 20.4,79.425 20.4,78.861 20.961,78.3 X6.2@21.05,78.3 ; v2(20.425,93.65) SB3.1@20.425,94.825 ; v1(20.525,58.825) v1@20.7,58.825 ; 21.85,75.75 18.356,75.75 16.4,77.706 16.4,78.694 17.451,79.745 17.945,79.745 18.425,80.225 22.1,80.225 ; C33.1@22.1,78.45 21.2,78.45 X6.2@21.05,78.3 ; C48.1@22.18,29.51 22.87,29.51 v1(23.02,29.66) 23.26,29.9 23.96,29.9 24.24,30.18 ; C44.2@22.43,38.61 v1@23.17,38.61 ; v2(22.825,76.4) 22.825,77.3 v2(23.15,77.625) ; v2(22.825,79.5) v2(24.5,79.5) v2(24.5,77.55) v2(24.5,76.2) 24.5,75.775 v2(25.35,74.925) v2(27.15,74.925) 27.6,74.925 28.625,73.9 v2(28.65,73.9) ; C31.1@22.9,85.145 v2(22.9,85.92) ; v1(23.62,70.78) U4.AB1@24.19,70.78 ; C51.2@24.52,16.73 24.54,16.71 v1(25.52,16.71) ; C49.2@24.53,18.67 24.59,18.73 v1(25.41,18.73) ; U6.G9@24.59,30.98 U6.G9@24.64,30.98 ; U6.F9@24.633,30.2 25.021,29.811 25.421,29.411 25.433,29.4 25.433,29.38 25.433,29.267 25.483,29.216 25.483,28.844 25.433,28.793 U6.D8@25.433,28.652 ; U6.F9@24.64,30.18 U6.F9@24.59,30.18 24.24,30.18 ; U6.G8@25.39,30.98 U6.G9@24.64,30.98 ; v2(25.75,75.9) C34.1@25.75,76.65 ; C32.1@26.25,85.145 v2(26.25,85.92) ; C38.1@28.025,76.575 28.025,76.1 28.325,75.8 v2(28.625,75.8) ; R10.2@28.4,110.2 v2(28.4,110.925) ; 29.925,77.675 30.325,77.275 C36.2@30.325,76.85 30.325,75.3 v2(30,74.975) v2(30.675,74.3) ; 29.925,77.696 v2(29.925,79.225) v2(33.375,79.225) v2@33.375,77.696 ; v2(31.35,73.325) 31.35,73.45 32.3,74.4 32.725,74.4 v2(33.3,74.975) 32.975,75.3 C37.1@32.975,76.85 32.975,77.296 33.364,77.686 v2@33.375,77.696 ; v2(33.375,77.675) v2@33.375,77.696 ; C5.1@33.675,110.2 v2(33.675,110.925) ; v2(37.775,109.3) B4.2@36.75,109.3 B4.1@36.75,113.75 v2(37.775,113.75) ; v1(38.99,55.98) U4.C19@39.39,56.38 ; v1(39.79,55.98) U4.B19@40.19,56.38 ; v2(45.9,61) 45.9,60.475 C40.1@46,60.375 ; C43.1@46,56 46.025,56.025 46.125,55.925 v2(46.775,55.925) ; C9.1@48.475,103.6 48.488,103.613 48.525,103.65 C6.1@48.525,104.65 ; v2(49.5,60.525) C39.2@50.3,60.525 ; v2(50,59.375) C41.1@50.8,59.375 ; C4.1@51.725,112.075 v2(51.725,112.8) ; U1.10@53.275,113.325 v2(53.275,114.05) ; v2@54.4,3.7 v2(54.5,3.7) R47.1@55.25,3.7 ; C13.1@55.3,99.15 C13.1@55.325,99.125 ; v2(56.6,7) R44.1@57.35,7 ; v2(56.625,11.125) R41.1@57.35,11.125 ; v2(56.633,10.124) 57.35,10.124 C56.2@57.358,10.124 ; C3.1@58.275,113.4 v2(58.275,114.125) ; R37.1@61.725,14.15 v2(61.725,14.875) ; v2(61.75,2.05) 62.6,2.05 R48.1@62.65,2 ; R40.1@64.825,14.15 v2(64.825,14.875) ; M1.21@65.775,11.775 v2(65.775,12.5) ; C2.1@70.5,114.4 v2(70.5,115.125) ; C55.1@71.025,13.975 v2(73.225,13.975) ; C18.1@78.395,95.7 v2@79.72,95.7 ; R14.1@80.275,100.5 v2(80.275,101.225) ; CN4.5@81.85,99.3 CN4.7@81.85,100.5 ; v2(82.575,103.975) LD6.1@83.825,103.975 v2(83.825,102.725) ; 10.225,116.625 10.25,116.6 ; 24.24,30.18 24.24,30.58 24.615,30.955 U6.G9@24.64,30.98
  Top Layer w0.35: v1@55.95,99.9 v1(56.025,99.975)
  Top Layer w0.4: C15.1@55.325,97.95 55.337,97.962 C15.1@55.35,97.975 ; v2@55.996,97.975 v2@56.027,98.006
  Top Layer w0.5: 40.275,100.525 40.3,100.55 C8.1@41.2,100.55 C8.1@41.2,100.3 ; v2(40.75,99.825) v2(41.55,99.825) ; v2@40.75,99.85 C8.1@41.2,100.3 ; v2(41.352,98.356) C14.1@42.227,98.356 ; 42.125,94.456 42.752,94.456 C21.1@42.802,94.456 ; C12.1@42.277,99.831 42.271,99.825 v2(41.55,99.825) ; v2(42.752,93.906) 42.752,94.406 C21.1@42.802,94.456 ; C20.2@44.202,94.51 C20.2@44.202,94.481 43.694,94.481 v2(43.525,94.65) 43.331,94.456 C21.1@42.802,94.456 ; v2(47.15,88.175) 47,88.325 C27.1@47,89.2 47.725,89.2 47.829,89.2 47.869,89.24 ; v2(47.725,89.625) 47.95,89.85 C25.1@49.075,89.85 49.075,89.175 49.175,89.075 ; 48.525,105.5 C6.1@48.525,104.65 ; C9.1@48.55,103.55 48.55,104.625 C6.1@48.525,104.65 ; 49.3,104.65 C6.1@48.525,104.65 ; v2(52.275,103.4) 52.4,103.275 C10.1@52.4,102.425 53.575,102.425 v2(53.6,102.45) ; 52.4,103.975 52.425,104 C7.1@52.425,104.825 ; 52.45,105.7 52.425,105.675 C7.1@52.425,104.825 ; 53.125,90.15 C24.1@53.125,90.825 ; 53.125,91.425 C24.1@53.125,90.825 ; v2(53.375,104.825) C7.1@52.425,104.825 ; 53.75,89.175 53.775,89.2 C26.1@54.325,89.2 ; 53.85,90.825 C24.1@53.125,90.825 ; 54.3,88.475 54.325,88.5 C26.1@54.325,89.2 ; 54.325,89.975 C26.1@54.325,89.2 ; C23.1@54.9,93.3 55.75,93.3 55.775,93.3 v2@55.8,93.275 ; C22.1@54.9,94.55 v2@55.7,94.55 ; v2@55.125,89.175 55.1,89.2 v2(55.05,89.2) C26.1@54.325,89.2 ; C67.1@55.3,99.9 v1@55.95,99.9 ; C17.1@55.325,96.375 v2(56.025,96.375) ; C16.1@55.325,97.175 v2(56.025,97.175) ; C13.1@55.325,99.125 v1(56.025,99.125) ; C15.1@55.35,97.975 v2@55.996,97.975 ; C19.1@55.352,95.581 56.025,95.581 v2@56.05,95.581 ; C11.1@55.421,100.675 v2(56.025,100.675) ; C8.1@41.2,100.3 41.2,100.175 v2(41.55,99.825)
  Top Layer w0.56: v2(42.375,116) C1.2@44.1,116 ; v2(44.1,114.275) C1.2@44.1,116 ; v2(44.1,117.725) C1.2@44.1,116 ; v2(58.95,115.55) D1.1@60.675,115.55 ; v2(60.675,117.275) D1.1@60.675,115.55 ; v2(62.4,115.55) D1.1@60.675,115.55
  Top Layer w0.6: LD1.2@46.75,116.675 v2(46.75,117.4) ; v2(73,7.6) C58.1@73,8.1 ; v2(74.125,6.975) C57.2@74.125,7.825 ; v2(85.3,18.7) v2(85.3,15.95) v2(85.3,8.8) v2(85.3,4.6) v2(85.3,0.7) v2(42.975,0.7) v2(36.65,0.7) v2(30.45,0.7) v2(23.675,0.7) v2(17.575,0.7) v2(11.65,0.7) v2(5.7,0.7) v2(0.7,0.7) v2(0.7,5.175) v2(0.7,8.775) v2(0.7,15.225) v2(0.7,21.35) v2(0.7,27.75) v2(0.7,33.825) v2(0.7,39.45) v2(0.7,44.075) v2(0.7,48.7) v2(0.7,53.375) v2(0.7,58.5) v2(0.7,62.825) v2(0.7,67.125) v2(0.7,71.275) v2(0.7,75.85) v2(0.7,80) v2(0.7,84.075) v2(0.7,88.025) v2(0.7,91.65) v2(0.7,94.85) v2(0.7,98.05) v2(0.7,101.45) v2(0.7,104.7) v2(0.7,107.725) v2(0.7,110.475) v2(0.7,112.975) v2(0.7,115.125) v2(0.7,117.05) v2(0.7,119.3) 2.675,119.3 v2(4.3,119.3) v2(8.575,119.3) 10.225,119.3 v2(13.625,119.3) v2(18.325,119.3) v2(26.15,119.3) v2(33.975,119.3) v2(41.125,119.3) v2(48.15,119.3) v2(55.025,119.3) v2(62.55,119.3) v2(69.05,119.3) v2(74.325,119.3) v2(79.9,119.3) v2(85.3,119.3) v2(85.3,115.175) v2(85.3,110.55) v2(85.3,103.65) 85.3,102.25 CN4.8@84.55,101.5 CN4.11@84.55,99 CN4.10@84.55,97 CN4.9@84.55,94.5 85.3,93.75 v2(85.3,90.55) v2(85.3,84.9) 85.3,83.1 85.3,82.1 85.3,80.1 v2(85.3,79.2) v2(85.3,73.975) v2(85.3,68.95) v2(85.3,63.35) v2(85.3,57.325) v2(85.3,51.85) v2(85.3,46.375) v2(85.3,41.775) v2(85.3,38.825) v2(85.3,36.1) v2(85.3,31.075) v2(85.3,26.35) v2(85.3,23.65) v2(85.3,21.175) v2@85.3,18.725
  Signal Layer 1 w0.2: v2(26.401,73.779) v2@26.448,73.825
  Signal Layer 2 w0.2: v1(54.675,61.8) v1@54.75,61.8 ; v1@62.9,60.65 v1(62.95,60.65)
  Signal Layer 2 w0.3: v2(11.015,103.46) v2@11.06,103.46
  Signal Layer 2 w0.6: v2(0.7,0.7) v2(5.7,0.7) v2(11.65,0.7) v2(17.575,0.7) v2(23.675,0.7) v2(30.45,0.7) v2(36.65,0.7) v2(42.975,0.7) v2(85.3,0.7) v2(85.3,4.6) v2(85.3,8.8) v2(85.3,15.95) v2(85.3,18.7) v2(85.3,21.175) v2(85.3,23.65) v2(85.3,26.35) v2(85.3,31.075) v2(85.3,36.1) v2(85.3,38.825) v2(85.3,41.775) v2(85.3,46.375) v2(85.3,51.85) v2(85.3,57.325) v2(85.3,63.35) v2(85.3,68.95) v2(85.3,73.975) v2(85.3,79.2) v2(85.3,84.9) v2(85.3,90.55) 85.3,93.75 CN4.9@84.55,94.5 CN4.8@84.55,101.5 85.3,102.25 v2(85.3,103.65) v2(85.3,110.55) v2(85.3,115.175) v2(85.3,119.3) v2(79.9,119.3) v2(74.325,119.3) v2(69.05,119.3) v2(62.55,119.3) v2(55.025,119.3) v2(48.15,119.3) v2(41.125,119.3) v2(33.975,119.3) v2(26.15,119.3) v2(18.325,119.3) v2(13.625,119.3) v2(8.575,119.3) v2(4.3,119.3) v2(0.7,119.3) v2(0.7,117.05) v2(0.7,115.125) v2(0.7,112.975) v2(0.7,110.475) v2(0.7,107.725) v2(0.7,104.7) v2(0.7,101.45) v2(0.7,98.05) v2(0.7,94.85) v2(0.7,91.65) v2(0.7,88.025) v2(0.7,84.075) v2(0.7,80) v2(0.7,75.85) v2(0.7,71.275) v2(0.7,67.125) v2(0.7,62.825) v2(0.7,58.5) v2(0.7,53.375) v2(0.7,48.7) v2(0.7,44.075) v2(0.7,39.45) v2(0.7,33.825) v2(0.7,27.75) v2(0.7,21.35) v2(0.7,15.225) v2(0.7,8.775) v2(0.7,5.175) v2(0.7,0.7)
  Signal Layer 3 w0.6: v2(0.7,0.7) v2(5.7,0.7) v2(11.65,0.7) v2(17.575,0.7) v2(23.675,0.7) v2(30.45,0.7) v2(36.65,0.7) v2(42.975,0.7) v2(85.3,0.7) v2(85.3,4.6) v2(85.3,8.8) v2(85.3,15.95) v2(85.3,18.7) v2(85.3,21.175) v2(85.3,23.65) v2(85.3,26.35) v2(85.3,31.075) v2(85.3,36.1) v2(85.3,38.825) v2(85.3,41.775) v2(85.3,46.375) v2(85.3,51.85) v2(85.3,57.325) v2(85.3,63.35) v2(85.3,68.95) v2(85.3,73.975) v2(85.3,79.2) v2(85.3,84.9) v2(85.3,90.55) 85.3,93.75 CN4.9@84.55,94.5 CN4.8@84.55,101.5 85.3,102.25 v2(85.3,103.65) v2(85.3,110.55) v2(85.3,115.175) v2(85.3,119.3) v2(79.9,119.3) v2(74.325,119.3) v2(69.05,119.3) v2(62.55,119.3) v2(55.025,119.3) v2(48.15,119.3) v2(41.125,119.3) v2(33.975,119.3) v2(26.15,119.3) v2(18.325,119.3) v2(13.625,119.3) v2(8.575,119.3) v2(4.3,119.3) v2(0.7,119.3) v2(0.7,117.05) v2(0.7,115.125) v2(0.7,112.975) v2(0.7,110.475) v2(0.7,107.725) v2(0.7,104.7) v2(0.7,101.45) v2(0.7,98.05) v2(0.7,94.85) v2(0.7,91.65) v2(0.7,88.025) v2(0.7,84.075) v2(0.7,80) v2(0.7,75.85) v2(0.7,71.275) v2(0.7,67.125) v2(0.7,62.825) v2(0.7,58.5) v2(0.7,53.375) v2(0.7,48.7) v2(0.7,44.075) v2(0.7,39.45) v2(0.7,33.825) v2(0.7,27.75) v2(0.7,21.35) v2(0.7,15.225) v2(0.7,8.775) v2(0.7,5.175) v2(0.7,0.7)
  Signal Layer 4 w0.6: v2(0.7,0.7) v2(5.7,0.7) v2(11.65,0.7) v2(17.575,0.7) v2(23.675,0.7) v2(30.45,0.7) v2(36.65,0.7) v2(42.975,0.7) v2(85.3,0.7) v2(85.3,4.6) v2(85.3,8.8) v2(85.3,15.95) v2(85.3,18.7) v2(85.3,21.175) v2(85.3,23.65) v2(85.3,26.35) v2(85.3,31.075) v2(85.3,36.1) v2(85.3,38.825) v2(85.3,41.775) v2(85.3,46.375) v2(85.3,51.85) v2(85.3,57.325) v2(85.3,63.35) v2(85.3,68.95) v2(85.3,73.975) v2(85.3,79.2) v2(85.3,84.9) v2(85.3,90.55) 85.3,93.75 CN4.9@84.55,94.5 CN4.8@84.55,101.5 85.3,102.25 v2(85.3,103.65) v2(85.3,110.55) v2(85.3,115.175) v2(85.3,119.3) v2(79.9,119.3) v2(74.325,119.3) v2(69.05,119.3) v2(62.55,119.3) v2(55.025,119.3) v2(48.15,119.3) v2(41.125,119.3) v2(33.975,119.3) v2(26.15,119.3) v2(18.325,119.3) v2(13.625,119.3) v2(8.575,119.3) v2(4.3,119.3) v2(0.7,119.3) v2(0.7,117.05) v2(0.7,115.125) v2(0.7,112.975) v2(0.7,110.475) v2(0.7,107.725) v2(0.7,104.7) v2(0.7,101.45) v2(0.7,98.05) v2(0.7,94.85) v2(0.7,91.65) v2(0.7,88.025) v2(0.7,84.075) v2(0.7,80) v2(0.7,75.85) v2(0.7,71.275) v2(0.7,67.125) v2(0.7,62.825) v2(0.7,58.5) v2(0.7,53.375) v2(0.7,48.7) v2(0.7,44.075) v2(0.7,39.45) v2(0.7,33.825) v2(0.7,27.75) v2(0.7,21.35) v2(0.7,15.225) v2(0.7,8.775) v2(0.7,5.175) v2(0.7,0.7)
  Bottom Layer w0.12: C115.2@18.56,55.28 C115.2@18.71,55.13 ; C82.1@26.99,64.78 C82.1@27.015,64.78 ; C105.1@31.69,59.155 C105.1@31.79,59.055 ; R103.1@43.26,36.67 R103.1@43.29,36.7 ; C116.2@46.26,53.56 C116.2@46.39,53.43
  Bottom Layer w0.15: v1(20.84,7.43) v1@20.85,7.42 ; v1(20.84,9.58) v1@20.86,9.6 ; v1(20.84,11.67) v1@20.86,11.69 ; v1(20.84,17.01) v1@20.85,17.02 ; v1(20.84,19.21) v1@20.86,19.19 ; v1(26.45,2.48) v1@26.49,2.52 ; C122.1@32.06,24.07 C122.1@32.22,23.91 ; C117.2@32.73,36.94 C117.2@32.84,36.83 ; C136.2@37.63,3.12 C136.2@37.67,3.16
  Bottom Layer w0.2: CN8.96@11.1,53.75 12.175,53.75 12.25,53.675 12.98,53.675 12.986,53.681 ; C115.2@18.71,55.13 v1(19.15,55.13) ; v2@19.335,4.475 v2(19.425,4.475) ; C113.1@22.465,57.355 22.74,57.08 v1(23.165,57.08) ; C121.2@22.66,26.33 23.12,26.33 v1(23.27,26.48) ; R108.1@24.99,15.44 24.99,14.83 25.15,14.67 v1(25.46,14.67) ; R98.2@25.459,63.575 25.785,63.575 v1(26.19,63.98) C82.1@26.99,64.78 ; C112.1@25.49,57.68 25.59,57.58 v1(26.19,57.58) C109.1@26.19,58.405 ; v1(27.79,66.38) v1(29.39,66.38) ; v1@27.9,66.27 v1@27.9,66.35 ; C94.1@28.29,61.655 C101.1@28.29,60.68 28.29,60.48 v1(27.79,59.98) 28.29,59.48 C107.1@28.29,59.155 28.29,59.13 28.59,58.83 v1(28.59,58.38) 28.59,58.335 28.945,57.98 29.556,57.98 29.576,58 29.825,58 v1@30.175,58.35 ; TP35.1@28.54,29.91 28.54,29.01 v1(28.59,28.96) ; 28.625,65.625 28.635,65.625 ; v1(29.34,62.33) 29.34,63.13 C87.1@29.39,63.18 29.39,63.88 v1(29.34,63.93) 29.34,64.73 v1(29.39,64.78) ; v1@29.375,64.8 29.175,64.8 28.635,65.34 28.635,65.625 ; TP37.1@29.42,12.29 29.63,12.08 v1@29.63,11.59 ; C106.1@29.99,59.155 30.19,58.955 v1(30.19,58.38) 30.19,58.335 30.545,57.98 31.156,57.98 31.176,58 31.4,58 31.725,58.325 v1@31.725,58.35 ; C75.1@30.725,70.275 30.725,69.845 v1(30.99,69.58) ; C80.1@30.825,65.625 30.07,66.38 v1(29.39,66.38) ; C80.1@30.89,65.58 30.99,65.48 v1(30.99,64.78) 30.99,64.08 30.94,64.03 30.89,63.98 30.99,63.88 v1(30.99,63.18) 30.99,62.455 30.89,62.355 30.94,62.355 30.952,62.343 30.99,62.305 30.99,62.28 v1(30.99,61.58) 30.99,60.78 C100.1@30.89,60.68 30.99,60.58 v1(30.99,59.98) ; v1(31.45,36.94) C117.2@32.73,36.94 ; v1(31.64,28.62) 31.84,28.62 C120.2@32.23,28.23 ; v1(31.64,29.38) 31.98,29.38 C119.2@32.23,29.13 ; v1(31.64,31.03) 31.8,30.87 C118.2@32.23,30.87 ; v1@31.775,58.35 32.125,58 32.404,58 32.424,57.98 33.08,57.98 v1@33.39,58.29 ; v1(31.79,58.38) C105.1@31.79,59.055 ; v1(32.22,23.31) C122.1@32.22,23.91 ; v1(32.59,59.98) C99.1@32.59,60.78 v1(32.59,61.58) C90.1@32.59,62.38 v1(32.59,63.18) C86.1@32.59,63.98 v1(32.59,64.78) C79.1@32.59,65.58 ; C131.2@33.08,7.52 33.39,7.52 v1(33.79,7.12) ; C76.1@33.25,69.625 33.25,68.92 v1(33.39,68.78) ; v1(33.39,58.38) v1@33.39,58.29 ; R102.2@33.58,51.21 33.91,51.21 v1(34.14,50.98) ; v1(33.79,8.72) v1(33.79,9.52) 34.45,9.52 C130.1@34.69,9.28 ; C78.1@34.29,65.58 34.29,64.88 v1(34.19,64.78) 34.19,64.38 34.29,64.28 C85.1@34.29,63.98 34.29,63.28 v1(34.19,63.18) 34.19,62.78 34.29,62.68 C89.1@34.29,62.38 34.29,61.68 v1(34.19,61.58) 34.19,60.88 C98.1@34.29,60.78 34.29,60.08 v1(34.19,59.98) 34.19,59.255 C104.1@34.29,59.155 34.365,59.08 C108.1@35.09,59.08 34.99,58.98 v1(34.99,58.38) 34.99,57.805 C110.1@35.065,57.73 ; C110.1@35.05,57.6 35.05,57.45 34.8,57.2 33.625,57.2 33.39,57.435 v1@33.39,58.29 ; C108.1@35.125,59.05 35.125,59.075 35.489,59.439 35.545,59.439 35.656,59.55 35.745,59.55 35.99,59.795 C103.1@35.99,59.98 35.99,60.28 35.69,60.58 v1(35.69,60.68) 35.99,60.98 C96.1@35.99,61.38 35.99,61.68 35.69,61.98 v1(35.69,62.08) 35.99,62.38 C88.1@35.99,62.78 35.99,63.18 v1(35.69,63.48) 35.99,63.78 C83.1@35.99,64.18 35.99,64.48 35.69,64.78 v1(35.69,64.88) 35.99,65.18 C77.1@35.99,65.58 ; v1(38.99,55.98) 39.26,55.98 39.74,56.46 C114.1@39.74,56.83 ; v2(42.55,4.5) v2@42.64,4.5 ; R103.1@43.29,36.7 v1(43.95,36.7) ; C116.2@46.39,53.43 v1(46.94,53.43) ; v1@66.2,93.675 v1(66.225,93.7) ; U10.35@69.225,92.7 69.225,92 69.4,91.825 69.775,91.825 ; 28.635,65.625 v1(29.39,66.38)
  Bottom Layer w0.3: v2(2.675,78.25) 2.75,78.25 CN8.17@4.9,78.25 ; v2(3.525,50.25) CN8.109@4.9,50.25 ; v2(3.525,51.75) CN8.103@4.9,51.75 ; v2(3.525,57.75) CN8.79@4.9,57.75 ; v2(3.675,81.675) 3.675,80.55 3.975,80.25 CN8.9@4.9,80.25 ; CN8.53@4.9,69.25 v2(6.275,69.25) ; CN8.49@4.9,70.25 v2(6.275,70.25) ; v2(9.725,53.75) CN8.96@11.1,53.75 ; v2(9.725,55.25) CN8.90@11.1,55.25 ; v2(9.725,56.75) CN8.84@11.1,56.75 12.1,56.75 12.375,57.025 ; v2(9.725,70.75) CN8.48@11.1,70.75 ; v2(9.725,71.75) CN8.44@11.1,71.75 ; v2(9.725,72.75) CN8.40@11.1,72.75 ; v1(9.725,77.15) 10.125,76.75 CN8.24@11.1,76.75 ; v2(11.825,107.65) v2(16.9,107.65) ; v1@18.69,9.98 18.82,10.11 C127.2@19.29,10.11 ; v1(20.84,13.84) C125.2@21.48,13.84 ; v1@20.85,7.42 C132.2@21.48,7.42 ; v1@20.85,17.02 C124.2@21.48,17.02 ; v1@20.86,9.6 C129.2@21.48,9.6 ; v1@20.86,11.69 C126.2@21.48,11.69 ; v1@20.86,19.19 C123.2@21.48,19.19 ; C97.1@22.575,60.275 22.95,59.9 v1(23.35,59.9) ; C93.1@23.65,61.08 23.65,60.65 23.35,60.35 v1(23.35,59.9) ; v1(25.39,59.98) 25.31,59.9 v1(23.35,59.9) ; v1@26.49,2.52 C140.2@26.49,3.16 ; v1(29.13,2.51) C139.2@29.13,3.16 ; v1(31.22,2.45) C138.2@31.22,3.16 ; v1@33.44,2.58 C137.2@33.44,3.16 ; v1(35.59,2.5) C135.2@35.59,3.19 ; v1(37.63,2.53) C136.2@37.63,3.12 ; v1(39.79,57.58) 39.91,57.7 C111.1@40.95,57.7 ; R97.2@46.25,67.775 v1(46.9,67.775) ; C128.2@46.31,9.8 46.83,9.8 v1(46.93,9.7) ; v1(54.675,61.8) 55.025,62.15 C92.1@55.55,62.15 ; C102.1@57.05,60.35 57.05,60.9 v1(57.275,61.125) ; v2(59.65,89.2) R73.1@60.375,89.2 ; v1(60.5,90.7) C69.1@61.225,90.7 U10.23@62.725,90.7 ; C81.2@61.625,65.025 62.825,65.025 v1(63,64.85) ; C95.2@61.975,61.575 62.225,61.575 v1(62.775,62.125) ; v1(63.05,81.1) R91.1@63.05,81.825 ; v1(64.575,78.225) C72.2@64.575,78.95 ; C74.2@65.625,77.45 65.55,77.525 v1(64.975,77.525) ; v1(66.225,82.05) C71.1@66.225,82.775 U10.8@66.225,84.2 ; v1(66.75,81.375) 65.55,81.375 65.3,81.125 v1(65.3,79.625) 65.3,78.4 64.975,78.075 v1(64.975,77.525) ; v2(68.775,93.975) C68.1@69.5,93.975 69.5,93.6 69.225,93.325 U10.35@69.225,92.7 ; C73.2@69.325,77.45 69.975,77.45 ; R88.2@69.975,81.9 69.975,81.25 ; C62.2@70.425,106.35 v2(70.425,107.075) ; U10.47@71.225,86.2 72.525,86.2 C70.1@72.625,86.1 v2(73.35,86.1) ; C64.1@71.575,105.85 v2(71.575,106.575) ; v1(72.775,74.75) CN7.31@74.9,74.75 ; v1(73.3,52.25) CN7.101@74.9,52.25 ; v1(73.3,52.75) CN7.99@74.9,52.75 ; v1(73.3,58.25) CN7.77@74.9,58.25 ; R74.2@73.475,87.7 v2(74.2,87.7) ; CN7.115@74.9,48.75 v1(76.5,48.75) ; R69.2@75.575,89.975 76.1,89.45 v2(76.1,89) ; U8.2@78.75,95.675 v2(79.72,95.675) ; v1(79.5,50.75) CN7.108@81.1,50.75 ; v1(79.5,53.75) CN7.96@81.1,53.75 ; v1(79.5,55.25) CN7.90@81.1,55.25 ; v1(79.5,58.75) CN7.76@81.1,58.75 ; v1(79.5,74.75) CN7.32@81.1,74.75 ; v1(64.975,77.525) 64.975,76.925 65.225,76.675 69.725,76.675 69.975,76.925 69.975,77.45 ; v1(68.925,81.25) 68.375,81.25 68.275,81.35 v1(68.275,81.9) R89.2@68.925,81.9 v1(68.925,81.25) ; v1(68.925,81.25) 69.975,81.25 ; 69.975,77.45 69.975,81.25
  Bottom Layer w0.5: C64.1@71.575,105.85 71.625,105.9 U9.2@73.025,105.9 ; v2(72.175,108.225) 72.35,108.4 C60.1@73.825,108.4 ; C61.2@76.9,106.35 77.4,105.85 C63.1@78.075,105.85 v2(78.8,105.85) ; R65.2@80.495,92.58 v2(80.495,93.305)
  Bottom Layer w0.6: v2(8,44.175) CN8.128@8,46.553 CN8.127@8,51.823 CN8.126@8,58.173 CN8.125@8,63.443 CN8.124@8,66.557 CN8.123@8,71.827 CN8.122@8,78.177 CN8.121@8,83.447 v2(8,85.2) ; v2(8.525,116.625) 8.55,116.6 BT1.2@10.25,116.6 ; v2(10.25,113.95) BT1.2@10.25,116.6 ; v2(11.95,116.6) BT1.2@10.25,116.6 ; v2(19.425,4.475) C134.1@20.9,4.475 ; C133.1@41,4.5 v2(42.55,4.5) ; CN9.9@70.4,3.675 v2(72.125,3.675) ; CN9.6@70.4,7.025 v2(72.125,7.025) ; v2(78,44.275) CN7.128@78,46.553 CN7.127@78,51.823 CN7.126@78,58.173 CN7.125@78,63.443 CN7.124@78,66.557 CN7.123@78,71.827 CN7.122@78,78.177 v2(78,81.45) CN7.121@78,83.447 ; v2(85.3,0.7) v2(42.975,0.7) v2(36.65,0.7) v2(30.45,0.7) v2(23.675,0.7) v2(17.575,0.7) v2(11.65,0.7) v2(5.7,0.7) v2(0.7,0.7) v2(0.7,5.175) v2(0.7,8.775) v2(0.7,15.225) v2(0.7,21.35) v2(0.7,27.75) v2(0.7,33.825) v2(0.7,39.45) v2(0.7,44.075) v2(0.7,48.7) v2(0.7,53.375) v2(0.7,58.5) v2(0.7,62.825) v2(0.7,67.125) v2(0.7,71.275) v2(0.7,75.85) v2(0.7,80) v2(0.7,84.075) v2(0.7,88.025) v2(0.7,91.65) v2(0.7,94.85) v2(0.7,98.05) v2(0.7,101.45) v2(0.7,104.7) v2(0.7,107.725) v2(0.7,110.475) v2(0.7,112.975) v2(0.7,115.125) v2(0.7,117.05) v2(0.7,119.3) v2(4.3,119.3) v2(8.575,119.3) 10.3,119.3 ; v2(85.3,4.6) v2(85.3,8.8) v2(85.3,15.95) ; v2(85.3,18.7) v2(85.3,21.175) v2(85.3,23.65) v2(85.3,26.35) v2(85.3,31.075) v2(85.3,36.1) v2(85.3,38.825) v2(85.3,41.775) v2(85.3,46.375) v2(85.3,51.85) v2(85.3,57.325) v2(85.3,63.35) v2(85.3,68.95) v2(85.3,73.975) v2(85.3,79.2) v2(85.3,84.9) v2(85.3,90.55) 85.3,93.75 CN4.9@84.55,94.5 CN4.8@84.55,101.5 85.3,102.25 v2(85.3,103.65) v2(85.3,110.55) v2(85.3,115.175) v2(85.3,119.3) v2(79.9,119.3) v2(74.325,119.3) v2(69.05,119.3) v2(62.55,119.3) v2(55.025,119.3) v2(48.15,119.3) v2(41.125,119.3) v2(33.975,119.3) v2(26.15,119.3) v2(18.325,119.3) v2(13.625,119.3) 10.3,119.3 ; BT1.2@10.25,116.6 10.25,119.25 10.3,119.3
  other v1: 33.44,2.5 18.67,9.98 29.63,11.48 34.17,15.12 28.99,27.38 24.99,29.78 23.17,38.6 39.79,59.98 27,67.975 67.275,93.725 47.154,95.036 48.904,95.036 50.629,95.036 48.029,95.686 49.754,95.686 47.154,96.261 48.879,96.286 50.629,96.286 48.029,96.886 49.754,96.886 47.179,97.461 48.904,97.461 50.629,97.461 48.275,99.7 47.025,100.375 43.4,100.975 46.6,102.375 49.725,102.4 51.45,102.425
  other v2: 49.1,2.075 2.2,2.1 5.2,2.1 8.2,2.1 11.2,2.1 14.2,2.1 17.2,2.1 20.2,2.1 47.2,2.1 50.2,2.1 74.2,2.1 77.2,2.1 59.575,2.175 51.025,5 3.7,5.1 6.7,5.1 9.7,5.1 12.7,5.1 15.7,5.1 75.7,5.1 78.7,5.1 81.7,5.1 53.2,7.2 2.2,8.1 5.2,8.1 8.2,8.1 11.2,8.1 14.2,8.1 17.2,8.1 77.2,8.1 80.2,8.1 83.2,8.1 42.9,8.2 50.975,9.15 3.7,11.1 6.7,11.1 9.7,11.1 12.7,11.1 15.7,11.1 48.7,11.1 72.7,11.1 78.7,11.1 81.7,11.1 84.7,11.1 52.875,11.325 44.375,11.975 50.85,13.775 57.325,14.075 2.2,14.1 5.2,14.1 8.2,14.1 11.2,14.1 14.2,14.1 17.2,14.1 74.2,14.1 77.2,14.1 80.2,14.1 83.2,14.1 67.6,14.875 56.225,15.3 58.7,15.4 71.325,15.625 3.7,17.1 6.7,17.1 9.7,17.1 12.7,17.1 15.7,17.1 48.7,17.1 69.7,17.1 78.7,17.1 63,17.2 58.525,17.3 65.7,17.325 56.525,17.35 61.05,17.45 50.575,19.625 63.45,19.725 67.65,20.025 2.2,20.1 5.2,20.1 8.2,20.1 11.2,20.1 14.2,20.1 17.2,20.1 71.2,20.1 74.2,20.1 77.2,20.1 80.2,20.1 83.2,20.1 58.5,20.225 56.525,21.1 61.35,21.575 43.975,21.8 3.7,23.1 6.7,23.1 9.7,23.1 12.7,23.1 48.7,23.1 69.7,23.1 72.7,23.1 78.7,23.1 81.7,23.1 84.7,23.1 66.2,23.325 63.525,23.475 58.475,23.525 56.525,24.85 61.3,25.025 2.2,26.1 5.2,26.1 8.2,26.1 11.2,26.1 50.675,26.1 71.2,26.1 74.2,26.1 77.2,26.1 80.2,26.1 83.2,26.1 67.05,26.375 44.05,26.425 58.425,27.2 63.425,27.25 82.225,27.55 56.525,28.1 61.3,28.45 3.7,29.1 6.7,29.1 9.7,29.1 12.7,29.1 48.7,29.1 69.7,29.1 72.7,29.1 78.7,29.1 81.7,29.1 84.7,29.1 66.125,29.2 58.55,30.55 63.425,30.65 44.2,30.725 50.55,31.875 2.2,32.1 5.2,32.1 8.2,32.1 11.2,32.1 66.35,32.1 71.2,32.1 74.2,32.1 77.2,32.1 80.2,32.1 83.2,32.1 52.275,32.125 56.5,32.25 61.475,32.3 58.55,34.25 63.325,34.3 51.625,34.5 3.7,35.1 6.7,35.1 9.7,35.1 48.7,35.1 69.7,35.1 72.7,35.1 78.7,35.1 81.7,35.1 84.7,35.1 66.5,35.275 44.225,35.425 56.45,36 61.275,36.15 52.45,37.375 2.2,38.1 5.2,38.1 8.2,38.1 11.2,38.1 71.2,38.1 74.2,38.1 77.2,38.1 80.2,38.1 83.2,38.1 58.525,38.75 63.45,38.8 67.825,38.825 50.075,39.35 61.35,40.675 3.7,41.1 6.7,41.1 9.7,41.1 56.45,41.1 69.7,41.1 72.7,41.1 78.7,41.1 81.7,41.1 84.7,41.1 65.25,41.375 58.475,42.325 67.475,42.5 54.625,43.05 63.575,43.275 2.2,44.1 5.2,44.1 11.2,44.1 71.2,44.1 74.2,44.1 77.2,44.1 80.2,44.1 83.2,44.1 50.175,44.475 61.25,44.65 65.175,44.8 52.625,44.95 55.55,45.2 49.8,46.575 3.7,47.1 6.7,47.1 9.7,47.1 48.7,47.1 69.7,47.1 72.7,47.1 75.7,47.1 81.7,47.1 84.7,47.1 67.625,47.3 62.75,47.375 58.175,47.425 1.825,47.5 52.45,47.925 50.375,49.175 12.925,49.425 6.675,50.075 65.125,51.375 47.675,51.875 57.525,51.875 7,52.225 14.975,52.35 3.7,53.1 63.7,53.1 66.7,53.1 69.7,53.1 3.525,54.7 55.538,54.887 44.825,55.125 57.025,55.175 66.125,55.425 72.975,55.95 57.35,58.3 65.525,58.425 69.075,58.475 6.7,71.1 38.5,73.875 9.4,75.05 17.05,78.575 12.75,78.85 17.2,83.525 13.3,83.575 25.175,83.8 22.3,84.05 17.475,85.975 13.325,86.45 30.725,86.65 33.925,86.675 54.725,88.375 4.075,88.95 47.725,88.975 33.25,89.775 54.725,90.075 52.175,90.975 33.25,91.15 8.425,91.475 33.275,92.5 4.6,92.925 55.75,93.225 55.75,94.525 8.45,95.15 4.075,95.375 56.025,95.575 13.025,97.4 16.725,97.85 56.025,97.925 5.625,98.775 38.8,99.8 22.275,101.7 8.625,102.225 40.65,103.95 44.425,103.975 49.575,104.525 49.575,105.275 4.25,105.8 49.45,106.3 82.65,109.575 82.7,113.075 20.5,113.525 17.05,116.75 23.925,116.8 3.35,116.875 83.175,117.15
